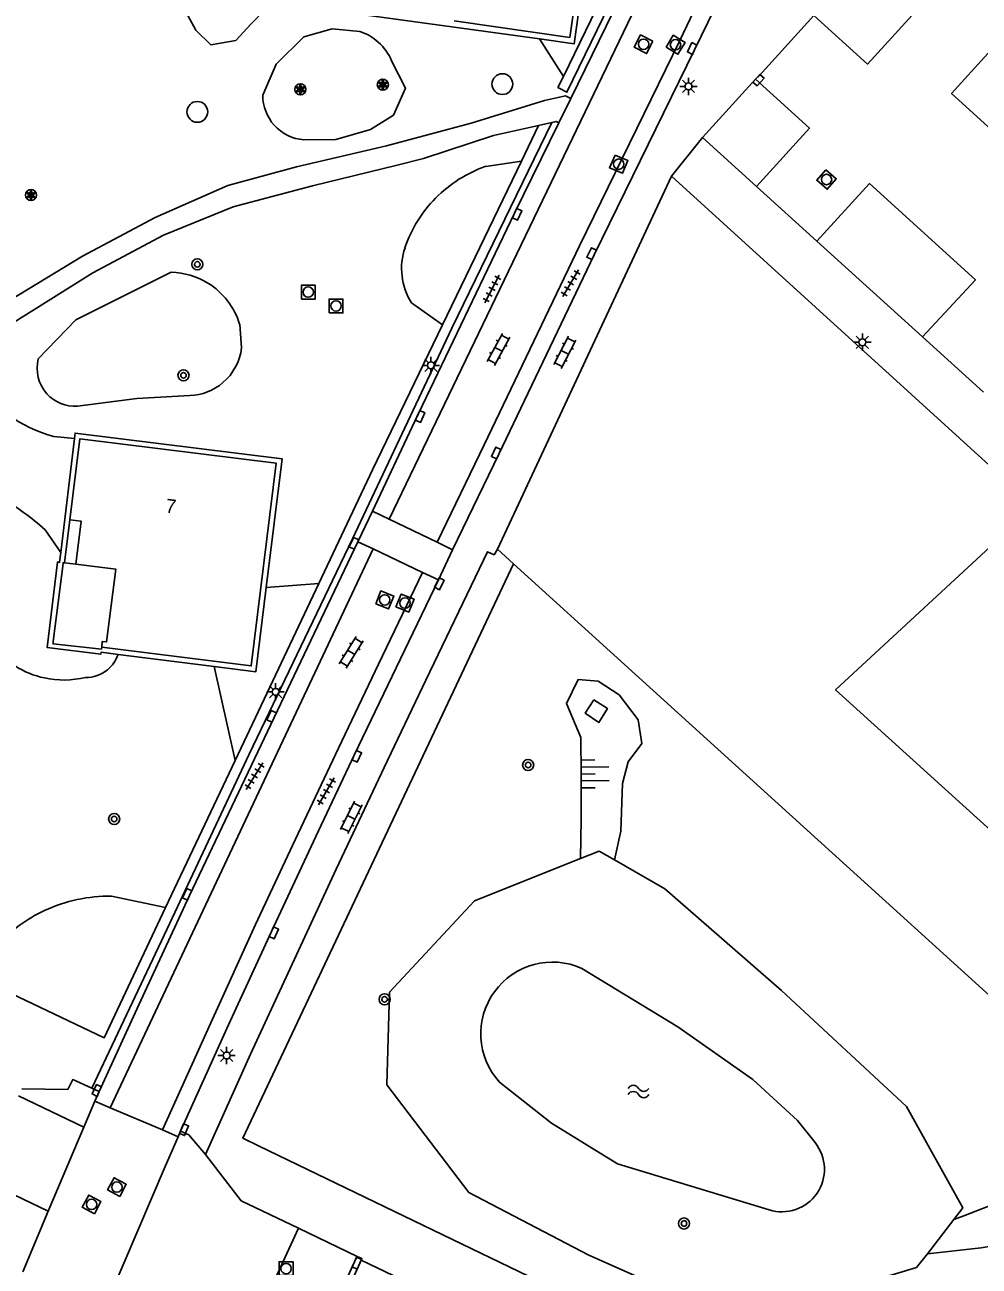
# Model space of a CAD drawing. Extents: x 124000 to 128010, y 398999 to 403000.
# Drawn here: x 126935.6 to 127004.4, y 399293.7 to 399383.3 of the extents above; entities that cross this region are included whole.
import ezdxf

# ---------------------------------------------------------------- set-up
doc = ezdxf.new("R2010")
doc.units = 0
for name, color, linetype in [('gg-afsc-erfafscheiding', 7, 'Continuous'), ('gg-afsc-faunaraster', 7, 'Continuous'), ('gg-afsc-muur', 7, 'Continuous'), ('gg-anno-huisnummerreeks BGT', 7, 'Continuous'), ('gg-bbg-hoofdgebouw', 7, 'Continuous'), ('gg-bbg-onder overbouw', 7, 'Continuous'), ('gg-bbg-pand overbouw', 7, 'Continuous'), ('gg-knt-BGT kruinlijn', 7, 'Continuous'), ('gg-knt-verharding', 7, 'Continuous'), ('gg-knt-verharding nz', 7, 'Continuous'), ('gg-kntw-bovenkant insteek waterloop', 7, 'Continuous'), ('gg-kntw-waterlijn', 7, 'Continuous'), ('gg-kwrk-uitstroombak niveau min 01', 7, 'Continuous'), ('gt-grn-groengrens', 7, 'Continuous'), ('gt-grn-weggrens', 7, 'Continuous'), ('gt-symb-boom', 7, 'Continuous'), ('gt-symb-klinker verharding', 7, 'Continuous'), ('gt-symb-kolk', 7, 'Continuous'), ('gt-symb-lichtmast', 7, 'Continuous'), ('gt-symb-rioolschacht', 7, 'Continuous'), ('gt-symb-solitaire heester', 7, 'Continuous'), ('gt-symb-talud symbool', 7, 'Continuous'), ('gt-symb-tegel verharding', 7, 'Continuous'), ('gt-symb-watersymbool', 7, 'Continuous')]:
    doc.layers.add(name, color=color, linetype=linetype)

# ---------------------------------------------------------------- blocks, each defined once
blk = doc.blocks.new('gt0-KOLK')
at = {"layer": 'gt-symb-kolk'}
blk.add_lwpolyline([(0, 0), (0.375, 0), (0.375, 0.4), (-0.375, 0.4), (-0.375, 0), (0, 0)], dxfattribs=at)
blk = doc.blocks.new('gt0-RS')
at = {"layer": 'gt-symb-rioolschacht'}
blk.add_lwpolyline([(-0.5, -0.5), (0.5, -0.5), (0.5, 0.5), (-0.5, 0.5)], close=True, dxfattribs=at)
blk.add_circle((0, 0), 0.375, dxfattribs=at)
blk = doc.blocks.new('gt0-LMAST')
at = {"layer": 'gt-symb-lichtmast'}
for p, q in [((-0.182, 0.173), (-0.447, 0.438)), ((-0.005, 0.246), (-0.005, 0.621)), ((0.172, 0.173), (0.437, 0.438)), ((-0.255, -0.004), (-0.63, -0.004)), ((-0.182, -0.181), (-0.447, -0.446)), ((-0.005, -0.254), (-0.005, -0.629)), ((0.437, -0.446), (0.172, -0.181)), ((0.245, -0.004), (0.62, -0.004))]:
    blk.add_line(p, q, dxfattribs=at)
blk.add_circle((-0.005, -0.004), 0.25, dxfattribs=at)
blk = doc.blocks.new('gt0-KL1')
at = {"layer": 'gt-symb-klinker verharding'}
for p, q in [((-1.15, 0.3), (1.15, 0.3)), ((-1, -0.3), (-1, 0.3)), ((-0.5, 0.3), (-0.5, 0.45)), ((0, -0.3), (0, 0.3)), ((0.5, 0.3), (0.5, 0.45)), ((1, -0.3), (1, 0.3)), ((-1.15, -0.3), (1.15, -0.3)), ((-0.5, -0.45), (-0.5, -0.3)), ((0.5, -0.45), (0.5, -0.3))]:
    blk.add_line(p, q, dxfattribs=at)
blk = doc.blocks.new('gt0-TEG1')
at = {"layer": 'gt-symb-tegel verharding'}
for p, q in [((-1.125, 0), (1.125, 0)), ((-0.9, -0.25), (-0.9, 0.25)), ((-0.45, -0.25), (-0.45, 0.25)), ((0, -0.25), (0, 0.25)), ((0.45, -0.25), (0.45, 0.25)), ((0.9, -0.25), (0.9, 0.25))]:
    blk.add_line(p, q, dxfattribs=at)
blk = doc.blocks.new('gt0-BOOM')
at = {"layer": 'gt-symb-boom'}
for radius in [0.4, 0.2]:
    blk.add_circle((0, 0), radius, dxfattribs=at)
blk = doc.blocks.new('gt0-TALUD_1')
at = {"layer": 'gt-symb-talud symbool'}
for p, q in [((-1, -1), (-1, 0)), ((-0.5, -2), (-0.5, 0)), ((0, -1), (0, 0)), ((0.5, -2), (0.5, 0)), ((1, -1), (1, 0))]:
    blk.add_line(p, q, dxfattribs=at)
blk = doc.blocks.new('gt0-WA')
at = {"layer": 'gt-symb-watersymbool'}
for centre, start, end in [((-0.323, 0.022), 28.07249, 151.92751), ((0.427, 0.422), 208.07248, 331.92751), ((-0.323, -0.428), 28.07249, 151.92751), ((0.427, -0.028), 208.07248, 331.92751)]:
    blk.add_arc(centre, 0.425, start, end, dxfattribs=at)
blk = doc.blocks.new('gt0-SH')
at = {"layer": 'gt-symb-solitaire heester'}
blk.add_circle((0, 0), 0.4, dxfattribs=at)
for centre, start, end in [((-0.346, 0.2), 270, 30), ((-0.346, -0.2), 330, 90), ((0, 0.4), 210, 330), ((0.346, 0.2), 150, 270), ((0.346, -0.2), 90, 210), ((0, -0.4), 30, 150)]:
    blk.add_arc(centre, 0.4, start, end, dxfattribs=at)

msp = doc.modelspace()

# ---------------------------------------------------------------- linework, layer by layer
at = {"layer": 'gg-afsc-erfafscheiding'}
msp.add_line((126938.308, 399344.43), (126937.607, 399338.794), dxfattribs=at)
for points in [[(126938.419, 399344.471), (126938.315, 399344.484), (126938.308, 399344.43)], [(126941.1, 399338.402), (126941.084, 399338.253), (126937.589, 399338.629), (126937.607, 399338.794)]]:
    msp.add_lwpolyline(points, dxfattribs=at)
at = {"layer": 'gg-afsc-faunaraster'}
for points in [[(126952.446, 399302.412), (126951.282, 399302.974), (126970.808, 399344.411)], [(127027.931, 399269.569), (126986.479, 399289.485), (126985.129, 399286.626), (126952.446, 399302.412)]]:
    msp.add_lwpolyline(points, dxfattribs=at)
at = {"layer": 'gg-afsc-muur'}
for p, q in [((126988.258, 399379.349), (126984.446, 399375.142)), ((126988.515, 399379.598), (126988.258, 399379.349)), ((126982.19, 399372.363), (127008.356, 399348.563)), ((126969.642, 399345.468), (126970.808, 399344.411))]:
    msp.add_line(p, q, dxfattribs=at)
msp.add_lwpolyline([(126970.808, 399344.411), (127033.563, 399287.503), (127039.514, 399294.047)], dxfattribs=at)
at = {"layer": 'gg-bbg-hoofdgebouw'}
for points in [[(126966.524, 399383.555), (126974.855, 399382.375), (126976.901, 399396.816), (126962.72, 399398.825), (126961.382, 399389.126)], [(126941.1, 399338.402), (126951.884, 399337.035), (126953.689, 399351.653), (126939.512, 399353.412), (126938.81, 399347.577)], [(127013.641, 399317.542), (126994.039, 399335.327), (127008.356, 399348.563)], [(126941.1, 399338.402), (126941.144, 399338.811), (126941.449, 399338.773), (126942.109, 399344.027), (126939.233, 399344.373)]]:
    msp.add_lwpolyline(points, dxfattribs=at)
at = {"layer": 'gg-bbg-onder overbouw'}
msp.add_lwpolyline([(126939.233, 399344.373), (126939.624, 399347.475), (126938.81, 399347.577)], dxfattribs=at)
at = {"layer": 'gg-bbg-pand overbouw'}
for p, q in [((126938.419, 399344.471), (126938.81, 399347.577)), ((126939.233, 399344.373), (126938.419, 399344.471))]:
    msp.add_line(p, q, dxfattribs=at)
at = {"layer": 'gg-knt-BGT kruinlijn'}
for points in [[(126975.63, 399323.147), (126975.693, 399325.994), (126975.685, 399329.243), (126975.651, 399331.888), (126974.619, 399334.335), (126975.476, 399336.072), (126976.917, 399335.945), (126978.428, 399334.944), (126979.804, 399333.146), (126980.064, 399331.435), (126979.08, 399330.115), (126978.666, 399328.567), (126978.547, 399325.115), (126978.082, 399323.062)], [(127002.561, 399297.11), (127003.283, 399297.377), (127008.091, 399299.254), (127011.176, 399298.953), (127011.203, 399296.204), (127004.531, 399295.066), (127000.661, 399294.65)]]:
    msp.add_lwpolyline(points, dxfattribs=at)
at = {"layer": 'gg-knt-verharding'}
for p, q in [((126974.932, 399377.966), (126982.392, 399393.196)), ((126983.512, 399392.676), (126961.833, 399347.631)), ((126974.075, 399376.214), (126974.932, 399377.966)), ((126972.614, 399376.026), (126973.565, 399376.242)), ((126984.446, 399375.142), (126988.328, 399371.624)), ((126982.19, 399372.363), (126969.642, 399345.468)), ((126988.328, 399371.624), (126992.682, 399367.677)), ((126992.682, 399367.677), (127000.308, 399360.765)), ((127000.308, 399360.765), (127004.696, 399356.788)), ((126937.653, 399353.581), (126939.133, 399353.446)), ((126939.133, 399353.446), (126938.145, 399345.231)), ((126959.569, 399345.998), (126960.624, 399348.193)), ((126961.833, 399347.631), (126960.624, 399348.193)), ((126937.014, 399346.858), (126938.145, 399345.231)), ((126959.569, 399345.998), (126960.68, 399345.479)), ((126966.412, 399345.423), (126965.3, 399345.969)), ((126960.68, 399345.479), (126941.715, 399305.178)), ((126960.68, 399345.479), (126964.239, 399343.773)), ((126965.381, 399343.246), (126966.412, 399345.423)), ((126965.381, 399343.246), (126964.239, 399343.773)), ((126949.208, 399336.991), (126942.279, 399337.869)), ((126935.338, 399306.54), (126938.659, 399306.492)), ((126940.923, 399306.335), (126940.384, 399306.58)), ((126940.594, 399305.65), (126940.923, 399306.335)), ((126939.804, 399303.779), (126940.594, 399305.65)), ((126941.715, 399305.178), (126940.594, 399305.65)), ((126937.247, 399297.722), (126939.804, 399303.779)), ((126945.474, 399303.576), (126946.606, 399303.088)), ((126945.683, 399300.932), (126946.606, 399303.088)), ((126946.606, 399303.088), (126946.775, 399303.491)), ((126943.708, 399296.317), (126945.683, 399300.932)), ((126935.401, 399293.351), (126937.247, 399297.722)), ((126959.515, 399294.452), (126955.286, 399296.484)), ((126939.91, 399287.443), (126943.708, 399296.317)), ((126957.739, 399289.582), (126959.825, 399294.179)), ((126959.825, 399294.179), (126965.128, 399291.652))]:
    msp.add_line(p, q, dxfattribs=at)
for points in [[(126962.989, 399399.168), (126962.321, 399399.27), (126960.211, 399383.976), (126972.683, 399382.256)], [(126965.3, 399345.969), (126968.685, 399352.981), (126975.552, 399367.327), (126982.798, 399382.158), (126986.999, 399390.985)], [(126988.192, 399390.368), (126983.866, 399381.484), (126976.613, 399366.685), (126969.736, 399352.307), (126966.412, 399345.423)], [(126972.683, 399382.256), (126975.182, 399381.911), (126976.193, 399389.131)], [(126929.948, 399360.676), (126939.707, 399366.6), (126944.946, 399369.391), (126950.187, 399371.678), (126955.154, 399373.042), (126961.64, 399374.538), (126967.759, 399376.185), (126973.042, 399377.808), (126974.551, 399378.152), (126974.932, 399377.966)], [(126974.075, 399376.214), (126970.886, 399369.695), (126963.686, 399354.684), (126960.624, 399348.193)], [(126973.565, 399376.242), (126973.876, 399376.312), (126974.075, 399376.214)], [(126932.55, 399360.559), (126934.406, 399361.591), (126940.45, 399365.395), (126945.545, 399368.109), (126950.59, 399370.147), (126956.302, 399371.659), (126962.407, 399373.15), (126964.301, 399373.647), (126969.357, 399375.289), (126972.614, 399376.026)], [(126952.962, 399342.704), (126954.113, 399351.984), (126939.179, 399353.828), (126939.133, 399353.446)], [(126940.923, 399306.335), (126943.781, 399312.608), (126947.443, 399320.479), (126953.535, 399333.325), (126959.569, 399345.998)], [(126938.145, 399345.231), (126938.059, 399344.514), (126937.91, 399344.532), (126937.168, 399338.366), (126941.033, 399337.876), (126941.052, 399338.025), (126942.279, 399337.869)], [(126969.642, 399345.468), (126969.397, 399345.054), (126968.934, 399345.272), (126964.481, 399336.007), (126961.479, 399329.718), (126958.019, 399322.393), (126951.834, 399309.029), (126948.593, 399301.796)], [(126964.239, 399343.773), (126961.064, 399337.171), (126958.176, 399331.113), (126954.86, 399324.087), (126952.204, 399318.395), (126948.964, 399311.307), (126945.474, 399303.576)], [(126946.775, 399303.491), (126950.251, 399311.163), (126953.336, 399317.875), (126956.551, 399324.743), (126959.32, 399330.605), (126965.381, 399343.246)], [(126952.962, 399342.704), (126952.206, 399336.611), (126949.208, 399336.991)], [(126940.384, 399306.58), (126939.012, 399307.206), (126938.659, 399306.492)], [(126948.593, 399301.796), (126947.384, 399303.22), (126946.775, 399303.491)], [(126955.286, 399296.484), (126951.168, 399298.459), (126948.593, 399301.796)], [(126950.89, 399286.435), (126951.962, 399289.241), (126955.286, 399296.484)], [(126945.724, 399263.532), (126949.744, 399272.836), (126953.746, 399281.791), (126959.322, 399294.05), (126959.515, 399294.452)], [(126959.515, 399294.452), (126959.873, 399294.307), (126959.825, 399294.179)]]:
    msp.add_lwpolyline(points, dxfattribs=at)
for centre, radius, start, end in [((126940.593, 399364.047), 10.871, 214.88067, 254.31097), ((126924.385, 399332.881), 18.838, 47.90156, 60.00339)]:
    msp.add_arc(centre, radius, start, end, dxfattribs=at)
at = {"layer": 'gg-knt-verharding nz'}
msp.add_line((126988.515, 399379.598), (126992.462, 399383.957), dxfattribs=at)
for points in [[(126992.462, 399383.957), (126996.341, 399380.445), (127008.519, 399393.835)], [(127012.876, 399389.88), (127002.395, 399378.326), (127010.006, 399371.4), (127020.51, 399382.951)], [(126988.328, 399371.624), (126992.142, 399375.822), (126988.258, 399379.349)], [(127000.308, 399360.765), (127004.117, 399364.887), (126996.491, 399371.828), (126992.682, 399367.677)]]:
    msp.add_lwpolyline(points, dxfattribs=at)
at = {"layer": 'gg-kntw-bovenkant insteek waterloop'}
for p, q in [((127002.561, 399297.11), (127000.661, 399294.65)), ((127000.661, 399294.65), (126999.882, 399293.642))]:
    msp.add_line(p, q, dxfattribs=at)
for points in [[(126975.63, 399323.147), (126976.991, 399323.69), (126978.082, 399323.062)], [(126999.882, 399293.642), (126990.313, 399290.77), (126984.156, 399291.041), (126976.24, 399294.552), (126967.583, 399299.057), (126961.676, 399306.826), (126961.868, 399313.507), (126967.986, 399320.095), (126975.63, 399323.147)], [(126978.082, 399323.062), (126981.716, 399320.972), (126990.134, 399313.635), (126999.157, 399305.263), (127003.215, 399297.956), (127002.561, 399297.11)]]:
    msp.add_lwpolyline(points, dxfattribs=at)
at = {"layer": 'gg-kntw-waterlijn'}
for points in [[(126992.554, 399302.659), (126991.276, 399304.258), (126988.076, 399307.214), (126982.646, 399311.001), (126975.742, 399315.219)], [(126969.802, 399307.026), (126973.536, 399304.074), (126978.301, 399301.137), (126989.234, 399297.817)]]:
    msp.add_lwpolyline(points, dxfattribs=at)
for centre, radius, start, end in [((126973.611, 399310.514), 5.165, 65.63397, 222.48111), ((126990.169, 399300.735), 3.064, 252.24114, 38.88456)]:
    msp.add_arc(centre, radius, start, end, dxfattribs=at)
at = {"layer": 'gg-kwrk-uitstroombak niveau min 01'}
msp.add_lwpolyline([(126976.588, 399334.599), (126975.983, 399333.636), (126976.969, 399332.971), (126977.572, 399333.978), (126976.588, 399334.599)], dxfattribs=at)
at = {"layer": 'gt-grn-groengrens'}
for p, q in [((126978.678, 399388.391), (126974.414, 399379.559)), ((126957.72, 399382.999), (126959.726, 399382.786)), ((126972.683, 399382.256), (126974.414, 399379.559)), ((126971.372, 399373.453), (126972.614, 399376.026)), ((126965.675, 399361.639), (126971.372, 399373.453)), ((126971.372, 399373.453), (126968.818, 399373.071)), ((126963.439, 399363.234), (126965.675, 399361.639)), ((126951.191, 399359.991), (126951.051, 399361.684)), ((126950.719, 399330.213), (126956.761, 399342.994)), ((126956.761, 399342.994), (126952.962, 399342.704)), ((126949.208, 399336.991), (126950.719, 399330.213)), ((126945.71, 399319.618), (126950.719, 399330.213)), ((126945.71, 399319.618), (126941.815, 399320.443))]:
    msp.add_line(p, q, dxfattribs=at)
for points in [[(126974.414, 399379.559), (126974.009, 399378.759), (126974.657, 399378.411), (126979.446, 399388.334), (126984.255, 399398.06), (126989.914, 399409.012), (126996.613, 399421.299), (127009.581, 399446.052), (127014.392, 399455.714), (127019.093, 399465.555)], [(126946.983, 399386.637), (126947.372, 399388.974), (126948.064, 399390.164), (126949.878, 399391.228), (126951.539, 399391.234), (126952.707, 399390.532), (126953.447, 399388.896), (126953.447, 399386.987), (126953.201, 399385.672), (126952.87, 399384.362), (126951.85, 399383.325), (126950.774, 399382.143), (126948.969, 399381.845), (126947.879, 399382.897), (126947.178, 399384.221), (126946.983, 399386.637)], [(126952.718, 399378.201), (126953.683, 399380.445), (126955.682, 399382.408), (126957.72, 399382.999)], [(126962.004, 399380.69), (126963.005, 399378.706), (126962.135, 399376.766), (126960.499, 399375.734), (126957.981, 399375.002), (126955.689, 399374.984)], [(126973.565, 399376.242), (126966.36, 399361.39), (126959.2, 399346.206), (126951.735, 399330.674), (126945.822, 399318.075), (126940.384, 399306.58)], [(126936.525, 399359.187), (126939.228, 399361.996), (126946.111, 399365.432)], [(126956.761, 399342.994), (126960.637, 399351.194), (126965.675, 399361.639)], [(126947.458, 399356.536), (126943.626, 399356.33), (126939.351, 399355.775)], [(126931.972, 399314.64), (126941.266, 399310.216), (126945.71, 399319.618)]]:
    msp.add_lwpolyline(points, dxfattribs=at)
for centre, radius, start, end in [((126958.62, 399379.305), 3.653, 48.25033, 72.37164), ((126958.613, 399379.289), 3.669, 22.44821, 48.3354), ((126970, 399379), 0.749, 0, 180), ((126970, 399379), 0.749, 180, 0), ((126955.93, 399378.189), 3.212, 179.77888, 222.10813), ((126948, 399377), 0.749, 0, 180), ((126948, 399377), 0.749, 180, 0), ((126955.936, 399378.197), 3.222, 222.13421, 265.59484), ((126971.876, 399364.186), 9.397, 108.99506, 135.44236), ((126971.902, 399364.166), 9.429, 135.46495, 161.20387), ((126967.397, 399365.708), 4.667, 161.29861, 212.00549), ((126945.968, 399360.104), 5.33, 58.42822, 88.4673), ((126945.977, 399360.124), 5.308, 17.08915, 58.39509), ((126947.3, 399360.451), 3.919, 310.47274, 353.25968), ((126939.18, 399358.512), 2.74, 165.72736, 222.1197), ((126947.298, 399360.457), 3.924, 272.3389, 310.43314), ((126939.183, 399358.511), 2.742, 222.08202, 273.51921), ((126939.969, 399338.631), 2.432, 309.61593, 341.75278), ((126938.361, 399342.553), 6.534, 237.58659, 257.66135), ((126939.994, 399338.607), 2.398, 268.36986, 309.51068), ((126938.36, 399342.552), 6.532, 257.67303, 283.87489), ((126941.706, 399309.252), 11.191, 89.44015, 114.99992), ((126941.677, 399309.313), 11.124, 114.99742, 136.93994)]:
    msp.add_arc(centre, radius, start, end, dxfattribs=at)
at = {"layer": 'gt-grn-weggrens'}
for p, q in [((126984.446, 399375.142), (126982.19, 399372.363)), ((126961.833, 399347.631), (126965.3, 399345.969)), ((126935.099, 399306.024), (126939.804, 399303.779)), ((126945.474, 399303.576), (126941.715, 399305.178)), ((126932.271, 399300.096), (126937.247, 399297.722))]:
    msp.add_line(p, q, dxfattribs=at)

# ---------------------------------------------------------------- block references
at = {"layer": 'gt-symb-boom'}
for p in [(126948, 399366), (126947, 399358), (126971.857, 399329.893), (126942, 399326), (126961.502, 399312.991), (126983.104, 399296.826)]:
    msp.add_blockref('gt0-BOOM', p, dxfattribs=at)
at = {"layer": 'gt-symb-klinker verharding'}
for p, rotation in [((126969.716, 399359.872), 61.590641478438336), ((126974.503, 399359.659), 62.615029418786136), ((126959.094, 399338.022), 58.24980309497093), ((126959.097, 399326.125), 63.43494882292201)]:
    msp.add_blockref('gt0-KL1', p, dxfattribs=dict(at, rotation=rotation))
at = {"layer": 'gt-symb-kolk'}
for p, rotation in [((126983.866, 399381.484), 64.02428534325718), ((126988.327, 399379.426), -132.161881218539), ((126970.886, 399369.695), -115.64307083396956), ((126976.613, 399366.685), 63.89617500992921), ((126963.889, 399355.114), -115.28348017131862), ((126969.736, 399352.307), 64.40857585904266), ((126959.48, 399345.802), 64.53665493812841), ((126965.276, 399343.048), -115.59142414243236), ((126953.535, 399333.325), 64.5883992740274), ((126959.32, 399330.605), -115.28348017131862), ((126947.443, 399320.479), 65.04884837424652), ((126953.336, 399317.875), -114.6951465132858), ((126940.923, 399306.335), 64.40857585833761), ((126946.849, 399303.669), -112.69475559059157), ((126959.322, 399294.05), -114.46065071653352)]:
    msp.add_blockref('gt0-KOLK', p, dxfattribs=dict(at, rotation=rotation))
at = {"layer": 'gt-symb-lichtmast'}
for p in [(126983.429, 399378.843), (126995.97, 399360.388), (126964.85, 399358.722), (126953.652, 399335.173), (126950.117, 399308.947)]:
    msp.add_blockref('gt0-LMAST', p, dxfattribs=at)
at = {"layer": 'gt-symb-rioolschacht'}
for p, rotation in [((126980.183, 399381.878), 152.7431282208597), ((126982.488, 399381.839), -30.71819066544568), ((126978.394, 399373.226), -113.46200022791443), ((126993.381, 399372.121), -130.9057260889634), ((126961.517, 399341.803), -21.950284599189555), ((126962.976, 399341.573), -22.02484593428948), ((126942.198, 399299.452), 62.153377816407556), ((126940.37, 399298.201), 61.64103655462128)]:
    msp.add_blockref('gt0-RS', p, dxfattribs=dict(at, rotation=rotation))
for p in [(126956, 399364), (126958, 399363), (126954.398, 399293.57)]:
    msp.add_blockref('gt0-RS', p, dxfattribs=at)
at = {"layer": 'gt-symb-solitaire heester'}
for p in [(126955.434, 399378.625), (126961.377, 399378.961), (126936, 399371)]:
    msp.add_blockref('gt0-SH', p, dxfattribs=at)
at = {"layer": 'gt-symb-talud symbool', "xscale": 1.0000844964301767, "yscale": 1.0000844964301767, "rotation": 90.74480317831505}
msp.add_blockref('gt0-TALUD_1', (126975.685, 399329.243), dxfattribs=at)
at = {"layer": 'gt-symb-tegel verharding'}
for p, rotation in [((126969.251, 399364.233), 62.53777281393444), ((126974.926, 399364.644), -120.66892664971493), ((126952.122, 399329.095), 58.24980309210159), ((126957.307, 399328.001), 59.949676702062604)]:
    msp.add_blockref('gt0-TEG1', p, dxfattribs=dict(at, rotation=rotation))
at = {"layer": 'gt-symb-watersymbool'}
msp.add_blockref('gt0-WA', (126979.767, 399306.352), dxfattribs=at)

# ---------------------------------------------------------------- texts
at = {"layer": 'gg-anno-huisnummerreeks BGT'}
msp.add_text('7', height=1, rotation=352.9, dxfattribs=at).set_placement((126945.661, 399348.115))

doc.saveas('drawing.dxf')
